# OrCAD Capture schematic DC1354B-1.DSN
size A; title: POSITIVE HIGH VOLTAGE HOT SWAP CONTROLLER; rev: 1; company: WITH SYNC FUNCTION; note: DEMO CIRCUIT 1354B
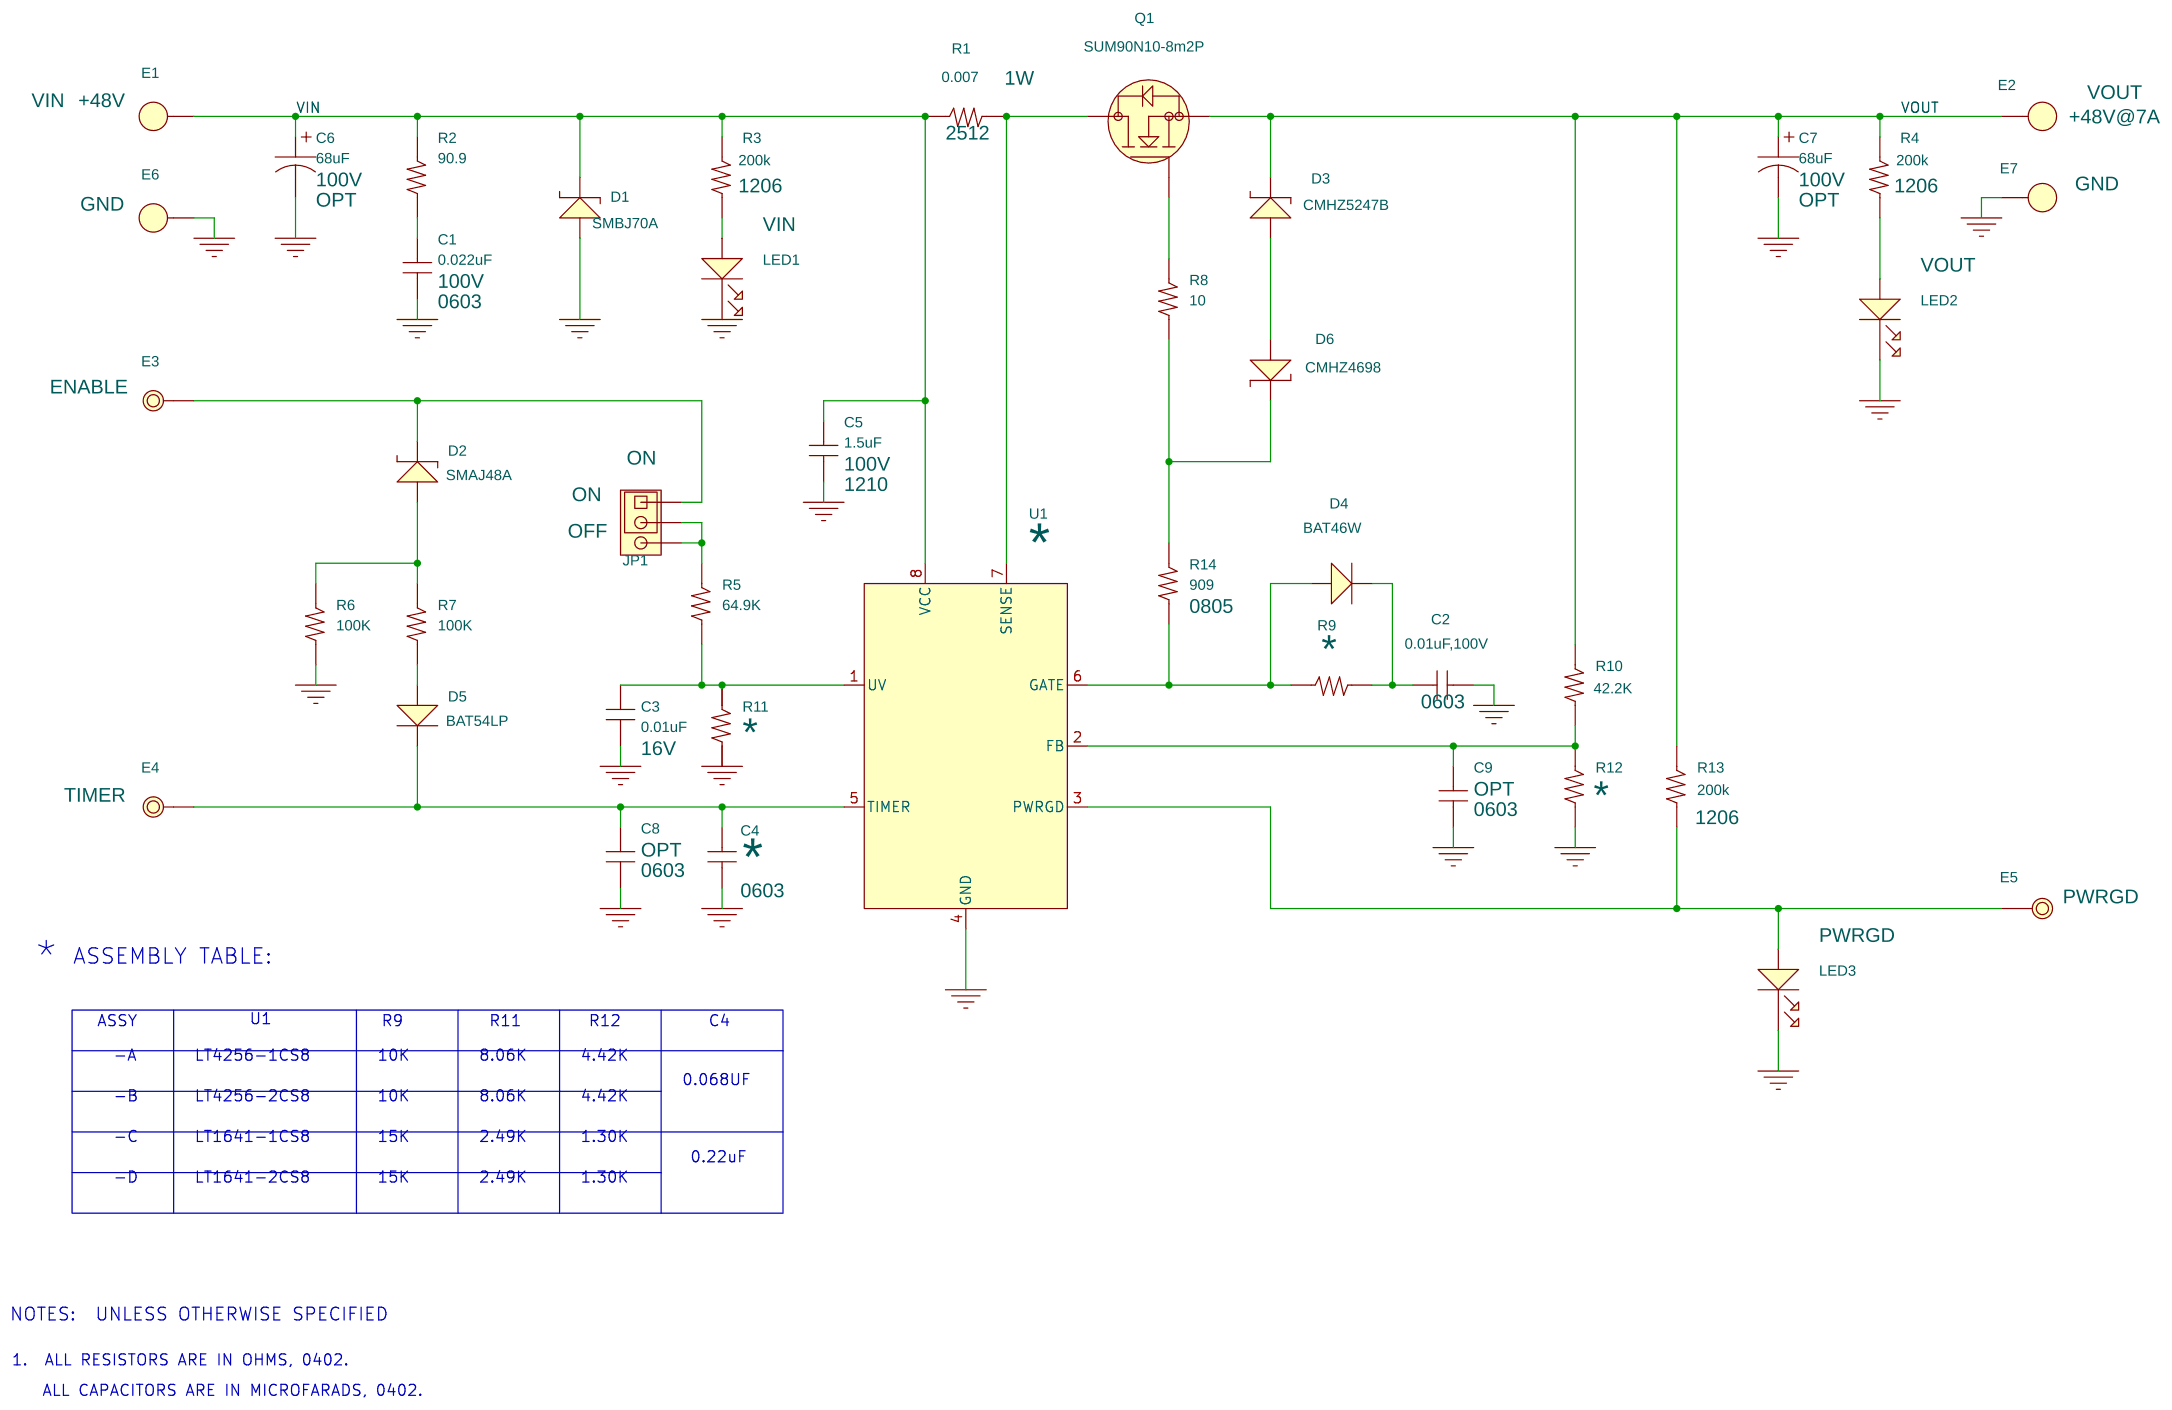
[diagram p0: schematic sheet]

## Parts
C1  0.022uF  [0603]
C2  0.01uF,100V  [0603]
C3  0.01uF  [0402]
C4  *  [0603]
C5  1.5uF  [1210]
C6  68uF  [C-SANYO-CE-AX-12.5X13.5]
C7  68uF  [C-SANYO-CE-AX-12.5X13.5]
C8  C-0603  [0805-0603]
C9  C-0603  [0805-0603]
D1  SMBJ70A  [SMB-DIODE]
D2  SMAJ48A  [SMA-DIODE]
D3  CMHZ5247B  [SOD123]
D4  BAT46W  [SOD123]
D5  BAT54LP  [DFN1006-2]
D6  CMHZ4698  [SOD123]
E1  PAD150-094  [PAD150-094]
E2  PAD150-094  [PAD150-094]
E3  PAD120-064  [PAD120-064]
E4  PAD120-064  [PAD120-064]
E5  PAD120-064  [PAD120-064]
E6  PAD150-094  [PAD150-094]
E7  PAD150-094  [PAD150-094]
JP1  HD1X3-079  [HD1X3-079]
LED1  WE, 150080GS75000  [LED-WE-GRN-150080GS75000]
LED2  WE, 150080GS75000  [LED-WE-GRN-150080GS75000]
LED3  WE, 150080GS75000  [LED-WE-GRN-150080GS75000]
Q1  SUM90N10-8m2P  [D2PAK]
R1  0.007  [2512]
R2  90.9  [0402]
R3  200k  [1206]
R4  200k  [1206]
R5  64.9K  [0402]
R6  100K  [0402]
R7  100K  [0402]
R8  10  [0402]
R9  *  [0402]
R10  42.2K  [0402]
R11  *  [0402]
R12  *  [0402]
R13  200k  [1206]
R14  909  [0805]
U1  *  [SO8]

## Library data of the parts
C1 C2 C5 = CAP-NP: COMPFIXED: 100V
C3 = CAP-NP: COMPFIXED: 16V
C4 = CAP-NP
C6 C7 = CAP: COMPFIXED: 100V; COMPGROUP: OPT
C8 C9 = CAP-NP: COMPFIXED: OPT; COMPGROUP: 0603
D1-D3 D6 = DIODE-ZENER
D4 D5 = DIODE
E1 = E: COMPFIXED: +48V; COMPGROUP: VIN
E2 = E: COMPFIXED: VOUT; COMPGROUP: +48V@7A
E3 = E-064: COMPFIXED: ENABLE
E4 = E-064: COMPFIXED: TIMER
E5 = E-064: COMPFIXED: PWRGD
E6 E7 = E: COMPGROUP: GND
JP1 = HD1X3: COMPFIXED: ON; COMPGROUP: ON; COMPKEY: OFF
LED1 = LED-WE-150080GS75000-GREEN: 1ST PART FIELD: VIN
LED2 = LED-WE-150080GS75000-GREEN: 1ST PART FIELD: VOUT
LED3 = LED-WE-150080GS75000-GREEN: 1ST PART FIELD: PWRGD
Q1 = MOSFET_N-DIODE-A_0
R1 = R: COMPFIXED: 1W
R2-R14 = R
U1 = LT4256-1_2CS8

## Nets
GND: C1.2 C2.2 C3.2 C4.2 C5.2 C6.2 C7.2 C8.2 C9.2 D1.2 E6.1(A) E7.1(A) LED1.1 LED2.1 LED3.1 R6.2 R11.2 R12.2 U1.4(GND)
VIN: C5.1 C6.1 D1.1 E1.1(A) R1.1 R2.1 R3.1 U1.8(VCC)
VOUT: C7.1 D3.1 E2.1(A) Q1.3 R4.1 R10.1 R13.1
N16603484: JP1.2 JP1.3 R5.1
N16603554: C3.1 R5.2 R11.1 U1.1(UV)
N16603849: D2.1 E3.1(A) JP1.1
N16604178: D5.2 R7.2
N16604235: D2.2 R6.1 R7.1
N16604350: C4.1 C8.1 D5.1 E4.1(A) U1.5(TIMER)
N16605645: LED1.2 R3.2
N16607157: Q1.2 R1.2 U1.7(SENSE)
N16607332: Q1.1 R8.1
N16607361: D4.2 R9.1 R14.2 U1.6(GATE)
N16607830: C2.1 D4.1 R9.2
N16608864: C9.1 R10.2 R12.1 U1.2(FB)
N16609219: LED2.2 R4.2
N16609300: E5.1(A) LED3.2 R13.2 U1.3(PWRGD)
N16616450: C1.1 R2.2
N16632991: D3.2 D6.2
N16633259: D6.1 R8.2 R14.1

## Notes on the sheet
- *
- ASSEMBLY TABLE:
- ASSY
- U1
- R9
- R11
- R12
- C4
- -A
- LT4256-1CS8
- 10K
- 8.06K
- 4.42K
- 0.068UF
- -B
- LT4256-2CS8
- 10K
- 8.06K
- 4.42K
- -C
- LT1641-1CS8
- 15K
- 2.49K
- 1.30K
- 0.22uF
- -D
- LT1641-2CS8
- 15K
- 2.49K
- 1.30K
- NOTES:  UNLESS OTHERWISE SPECIFIED
- 1.  ALL RESISTORS ARE IN OHMS, 0402.
- ALL CAPACITORS ARE IN MICROFARADS, 0402.
